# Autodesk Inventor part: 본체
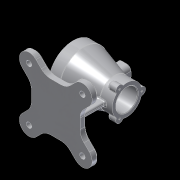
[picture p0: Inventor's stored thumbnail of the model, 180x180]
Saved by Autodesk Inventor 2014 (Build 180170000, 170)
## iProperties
Created: 2018-03
Part Number: 본체
Material: 알루미늄 6061
Document SubType Name: Modeling
Designer: user
Density: 2.71 g/cm^3
Appearance: 알루미늄 - 평지
Mass: 1013.02 g
Surface Area: 853.052 cm^2
Volume: 373.807 cm^3
Author: user
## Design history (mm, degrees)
sketch "스케치1"
  geometry: L1 (-45, 45)-(-19.544, 45); L2 (45, 45)-(45, 19.544); L3 (45, -45)-(19.544, -45); L4 (-45, -45)-(-45, -19.544); L5 (-45, 45)-(45, -45); L6 (45, 45)-(-45, -45); L7 (49.497, -49.497)-(-49.497, 49.497); L8 (49.497, -49.497)-(-49.497, 49.497); L9 (62.225, -36.77)-(45, -19.544); L10 (-62.225, 36.77)-(-45, 19.544); L11 (49.497, 49.497)-(-49.497, -49.497); L12 (49.497, 49.497)-(-49.497, -49.497); L13 (36.77, 62.225)-(19.544, 45); L14 (-36.77, -62.225)-(-19.544, -45); L15 (19.544, -45)-(-19.544, -45); L16 (45, -19.544)-(45, -45); L17 (45, 19.544)-(45, -19.544); L18 (19.544, 45)-(45, 45); L19 (45, 19.544)-(62.225, 36.77); L20 (19.544, -45)-(36.77, -62.225); L21 (-19.544, -45)-(-45, -45); L22 (-45, -19.544)-(-45, 19.544); L23 (-45, -19.544)-(-62.225, -36.77); L24 (-45, 19.544)-(-45, 45); L25 (-19.544, 45)-(-36.77, 62.225); L26 (-19.544, 45)-(19.544, 45); C1 r 5 at (49.497, -49.497); C2 r 5 at (-49.497, 49.497); C3 r 5 at (-49.497, -49.497); C4 r 5 at (49.497, 49.497); A1 r 70 centre (0, 0) between (49.497, -49.497) and (-49.497, 49.497); A2 r 18 centre (49.497, -49.497) between (36.77, -62.225) and (62.225, -36.77); A3 r 18 centre (-49.497, 49.497) between (-36.77, 62.225) and (-62.225, 36.77); A4 r 18 centre (49.497, 49.497) between (62.225, 36.77) and (36.77, 62.225); A5 r 18 centre (-49.497, -49.497) between (-62.225, -36.77) and (-36.77, -62.225); 3 further points
  constraints: 56 end point, 26 parallel, 16 tangent, 13 point on circle, 10 perpendicular, 9 centre point, 6 coincident, 5 midpoint, 3 horizontal, 1 collinear, 1 point on line
  dimensions: "d0" = 140 diameter of A1; "d1" = 90 distance of L2.start L3.start; "d2" = 90 distance of L3.start L4.start; "d4" = 10 diameter of C2; "d5" = 10 diameter of C1; "d7" = 10 diameter of C4; "d8" = 10 diameter of C3; "d9" = 36 distance between parallel lines of L20 L9; "d10" = 36 distance between parallel lines of L23 L14
extrude "돌출1" new body sketch "스케치1" distance "d11" = 12; taper "d12" = 0 deg
fillet "모깎기1" dims "d13" = 25
chamfer "모따기1" distance "d14" = 3; stored, may be unused: second distance "d15" = 2, angle "d16" = 45 deg
sketch "스케치2"
  geometry: L1 (-50, 82)-(50, 82); L2 (-49, 117)-(-30, 117); L3 (-27, 114)-(-27, 111); L4 (-24, 108)-(17, 108); L5 (20, 105)-(20, 105); L6 (23, 102)-(49, 102); L7 (50, 103)-(50, 109.5); L8 (50, 109.5)-(27, 109.5); L9 (27, 109.5)-(-30, 127); L10 (-30, 127)-(-50, 127); L11 (-50, 127)-(-50, 118); L12 (49, 102)-(50, 103); L13 (-49, 117)-(-50, 118); A1 r 3 centre (-30, 114) between (-27, 114) and (-30, 117); A2 r 3 centre (-24, 111) between (-27, 111) and (-24, 108); A3 r 3 centre (17, 105) between (20, 105) and (17, 108); A4 r 3 centre (23, 105) between (20, 105) and (23, 102); 6 further points
  constraints: 26 end point, 12 point on line, 8 parallel, 8 point on circle, 8 tangent, 4 centre point, 3 equal radius, 1 horizontal, 1 perpendicular
  dimensions: "d18" = 82 distance from line of L1 point (0, 0); "d19" = 100 distance of L1.start L1.end; "d20" = 50 horizontal distance of point (0, 0) L1.start; "d21" = 70 diameter of L2 L1; "d22" = 52 diameter of L4 L1; "d23" = 40 diameter of L6 L1; "d24" = 55 diameter of L8 L1; "d25" = 90 diameter of L10 L1; "d26" = 20 distance of L9.end L10.end; "d27" = 23 distance of point (-50, 117) point (-27, 117); "d28" = 47 distance of point (-27, 108) point (20, 108); "d29" = 77 distance from line of L11 L8.end; "d30" = 3 radius of A1; "d31" = 1 distance of L6.end point (50, 102); "d32" = 1 distance of L7.start point (50, 102) (= d31); "d34" = 1 distance of L2.start point (-50, 117); "d35" = 1 distance of L11.end point (-50, 117) (= d34)
revolve "회전1" sketch "스케치2" stored, may be unused: angle "d33" = 90 deg
sketch "스케치3"
  geometry: C1 r 45 at (0, 0) reference; 2 further points
  constraints: 1 vertical alignment
  dimensions: "d36" = 40 distance of C1.centre point (0, 40)
hole "구멍1" sketch "스케치3" at (0, 40) diameter "d37" = 3.242; stored, may be unused: countersink angle "d41" = 90 deg, drill point angle "d43" = 118 deg; dims "d38" = 9, "d39" = 4, "d40" = 2, "d42" = 11
sketch "스케치4"
  geometry: C1 r 21 at (0, 0) reference; A1 r 27.5 centre (0, 0) between (0, 27.5) and (6.943, 26.609) reference; A2 r 7 centre (0, 27.5) between (6.943, 26.609) and (-6.943, 26.609); 1 further point
  constraints: 5 point on circle, 1 centre point, 1 vertical alignment
  dimensions: "d47" = 14 diameter of A2
extrude "돌출2" join sketch "스케치4" distance "d48" = 15; taper "d49" = 0 deg
hole "구멍2" diameter "d52" = 3.242; stored, may be unused: countersink angle "d56" = 90 deg, drill point angle "d58" = 118 deg; dims "d50" = 10, "d51" = 10, "d53" = 9, "d54" = 4, "d55" = 2, "d57" = 11
fillet "모깎기2" dims "d59" = 1, "d60" = 3
fillet "모깎기3" dims "d64" = 3
node "작업 평면1"
sketch "스케치5"
  geometry: L1 (-4.5, 12.5)-(4.5, 12.5); L2 (12.5, 4.5)-(12.5, -4.5); L3 (4.5, -12.5)-(-4.5, -12.5); L4 (-12.5, -4.5)-(-12.5, 4.5); L5 (-12.5, 12.5)-(12.5, -12.5); L6 (12.5, 12.5)-(-12.5, -12.5); A1 r 8 centre (-4.5, 4.5) between (-4.5, 12.5) and (-12.5, 4.5); A2 r 8 centre (4.5, 4.5) between (12.5, 4.5) and (4.5, 12.5); A3 r 8 centre (4.5, -4.5) between (4.5, -12.5) and (12.5, -4.5); A4 r 8 centre (-4.5, -4.5) between (-12.5, -4.5) and (-4.5, -12.5); 1 further point
  constraints: 12 end point, 8 point on circle, 8 point on line, 8 tangent, 4 centre point, 3 equal radius, 2 midpoint, 2 parallel, 1 horizontal, 1 perpendicular
  dimensions: "d66" = 25 distance of L6.start L5.end; "d67" = 25 distance of L5.end L6.end; "d68" = 8 radius of A1
extrude "돌출3" join sketch "스케치5" stored distance "d69" = 12; taper "d70" = 0 deg
sketch "스케치6"
  geometry: L1 (4.5, -7.5)-(-4.5, -7.5); L2 (-7.5, -4.5)-(-7.5, 4.5); L3 (-4.5, 7.5)-(4.5, 7.5); L4 (7.5, 4.5)-(7.5, -4.5); L5 (7.5, -7.5)-(-7.5, 7.5); L6 (-7.5, -7.5)-(7.5, 7.5); A1 r 3 centre (-4.5, 4.5) between (-4.5, 7.5) and (-7.5, 4.5); A2 r 3 centre (4.5, 4.5) between (7.5, 4.5) and (4.5, 7.5); A3 r 3 centre (4.5, -4.5) between (4.5, -7.5) and (7.5, -4.5); A4 r 3 centre (-4.5, -4.5) between (-7.5, -4.5) and (-4.5, -7.5); 1 further point
  constraints: 12 end point, 8 point on circle, 8 point on line, 8 tangent, 4 centre point, 3 equal radius, 2 midpoint, 2 parallel, 1 horizontal, 1 perpendicular
  dimensions: "d71" = 15 distance of L6.start L5.end; "d72" = 15 distance of L5.end L6.end; "d73" = 3 radius of A1
extrude "돌출4" cut sketch "스케치6" stored distance "d74" = 12; taper "d75" = 0 deg
chamfer "모따기2" distance "d76" = 1; stored, may be unused: second distance "d77" = 2, angle "d78" = 45 deg
fillet "모깎기4" dims "d79" = 1
sketch "스케치7"
  geometry: L1 (37, -4)-(-37, -4); L2 (-37, -4)-(-37, 4); L3 (-37, 4)-(37, 4); L4 (37, 4)-(37, -4); L5 (37, -4)-(-37, 4); L6 (-37, -4)-(37, 4); 1 further point
  constraints: 12 end point, 2 midpoint, 2 parallel, 1 horizontal, 1 perpendicular
  dimensions: "d80" = 8 distance of L1.end L2.end; "d81" = 74 distance of L1.start L1.end
extrude "돌출5" join sketch "스케치7" stored distance "d82" = 0; taper "d83" = 0 deg
sketch "스케치8"
  geometry: L1 (4, -24)-(-4, -24); L2 (-4, -24)-(-4, 24); L3 (-4, 24)-(4, 24); L4 (4, 24)-(4, -24); L5 (4, -24)-(-4, 24); L6 (-4, -24)-(4, 24); 1 further point
  constraints: 12 end point, 2 midpoint, 2 parallel, 1 horizontal, 1 perpendicular
  dimensions: "d84" = 8 distance of L2.end L3.end; "d85" = 48 distance of L1.end L2.end
extrude "돌출6" join sketch "스케치8" stored distance "d86" = 12; taper "d87" = 0 deg
feature "면 기울기1" dims angle "d88" = 5 deg
fillet "모깎기5" dims "d89" = 3
fillet "모깎기6" dims "d90" = 3
sketch "스케치9"
  geometry: L1 (45, -9.189)-(45, 9.189) reference; 2 further points
  constraints: 1 other
  dimensions: "d91" = 35 distance of point (0, -35) point (0, 0); "d92" = 45 distance from line of point (0, -35) L1
feature "엠보싱1" sketch "스케치9" dims "d0" = 140, "d1" = 90, "d2" = 90, "d4" = 10, "d5" = 10, "d7" = 10, "d8" = 10, "d9" = 36, "d10" = 36, "d93" = 0.5, "d94" = 0
node "솔리드1"
pattern_circular "원형 패턴1" dims angle "d45" = 360 deg
pattern_circular "원형 패턴2" dims "d62" = 360 deg
other parameters: "d65" = 127
